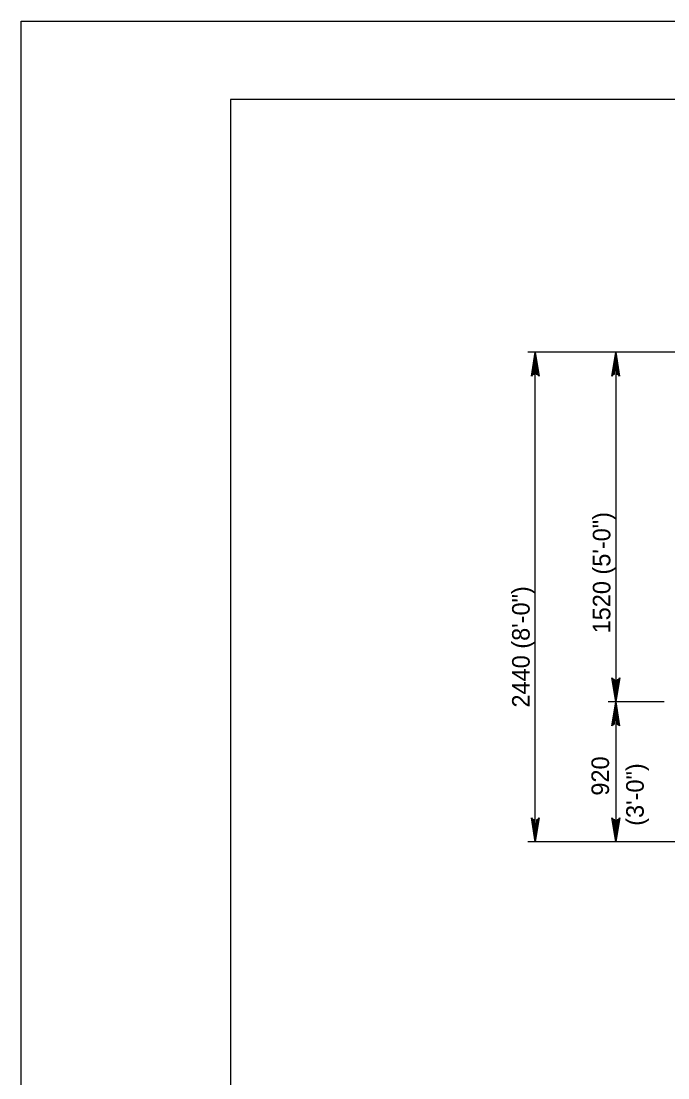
# Model space of a CAD drawing. Extents: x -4 to 901, y -468 to 720.
# Drawn here: x -3.7 to 119.8, y 518.1 to 720 of the extents above; entities that cross this region are included whole.
import ezdxf

# ---------------------------------------------------------------- set-up
doc = ezdxf.new("R2010")
doc.units = 0
for name, color, linetype in [('1', 7, 'Continuous'), ('2', 7, 'Continuous'), ('3', 7, 'Continuous'), ('PLT-BNDY', 7, 'Continuous')]:
    doc.layers.add(name, color=color, linetype=linetype)

msp = doc.modelspace()

# ---------------------------------------------------------------- linework, layer by layer
at = {"layer": '1'}
msp.add_lwpolyline([(822.258, 141.027875), (822.258, 705.027875), (36.258, 705.027875), (36.258, 141.027875), (822.258, 141.027875), (822.258, 167.386875), (622.258, 167.386875), (622.258, 232.064375), (822.258, 232.064375), (822.258, 261.027875), (622.258, 261.027875), (622.258, 141.027875), (701.0595, 141.027875), (701.0595, 167.386875), (701.0595, 141.027875), (778.0595, 141.027875), (778.0595, 167.386875), (778.0595, 155.070375), (822.258, 155.070375)], dxfattribs=at)
at = {"layer": '2'}
for p, q in [((138.8405, 656.795125), (93.0485, 656.795125)), ((94.4885, 563.195125), (94.4885, 656.795125)), ((109.8825, 656.795125), (109.8825, 589.941125)), ((119.1105, 589.941125), (108.4425, 589.941125)), ((109.8825, 589.941125), (109.8825, 563.195125)), ((148.4405, 563.195125), (93.0485, 563.195125))]:
    msp.add_line(p, q, dxfattribs=at)
for points in [[(93.9425, 652.435125), (94.2585, 652.597125), (94.4885, 656.795125), (93.9425, 652.435125), (93.7505, 652.211125), (94.4885, 656.795125), (94.6965, 652.601125), (95.0085, 652.447125), (94.4885, 656.795125), (95.2165, 652.211125), (95.0085, 652.447125)], [(109.3365, 652.435125), (109.6525, 652.597125), (109.8825, 656.795125), (109.3365, 652.435125), (109.1445, 652.211125), (109.8825, 656.795125), (110.0905, 652.601125), (110.4025, 652.447125), (109.8825, 656.795125), (110.6105, 652.211125), (110.4025, 652.447125)], [(110.4305, 594.299125), (110.1145, 594.137125), (109.8825, 589.941125), (110.4305, 594.299125), (110.6225, 594.523125), (109.8825, 589.941125), (109.6765, 594.135125), (109.3645, 594.287125), (109.8825, 589.941125), (109.1545, 594.523125), (109.3645, 594.287125)], [(109.3365, 585.581125), (109.6525, 585.745125), (109.8825, 589.941125), (109.3365, 585.581125), (109.1445, 585.359125), (109.8825, 589.941125), (110.0905, 585.747125), (110.4025, 585.595125), (109.8825, 589.941125), (110.6105, 585.359125), (110.4025, 585.595125)], [(95.0365, 567.553125), (94.7205, 567.391125), (94.4885, 563.195125), (95.0365, 567.553125), (95.2285, 567.777125), (94.4885, 563.195125), (94.2825, 567.387125), (93.9705, 567.541125), (94.4885, 563.195125), (93.7605, 567.777125), (93.9705, 567.541125)], [(110.4305, 567.553125), (110.1145, 567.391125), (109.8825, 563.195125), (110.4305, 567.553125), (110.6225, 567.777125), (109.8825, 563.195125), (109.6765, 567.387125), (109.3645, 567.541125), (109.8825, 563.195125), (109.1545, 567.777125), (109.3645, 567.541125)]]:
    msp.add_lwpolyline(points, dxfattribs=at)
at = {"layer": 'PLT-BNDY'}
msp.add_lwpolyline([(-3.742, 720.027875), (837.258, 720.027875), (837.258, 126.027875), (-3.742, 126.027875)], close=True, dxfattribs=at)

# ---------------------------------------------------------------- texts
at = {"layer": '3'}
for s, p in [('1520 (5\'-0")', (108.848, 603.042875)), ('2440 (8\'-0")', (93.4235, 588.870875)), ('920', (108.5885, 572.039875)), ('(3\'-0")', (115.2285, 566.281625))]:
    msp.add_text(s, height=3.36, rotation=90, dxfattribs=at).set_placement(p)

doc.saveas('drawing.dxf')
